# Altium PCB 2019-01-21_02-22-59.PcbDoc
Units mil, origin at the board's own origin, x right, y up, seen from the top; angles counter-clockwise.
Board outline 1500 x 2000 mil, 4 copper layers (Top Layer, MidLayer1, MidLayer2, Bottom Layer); 21 components, 11 nets, 49 pads, 30 vias.
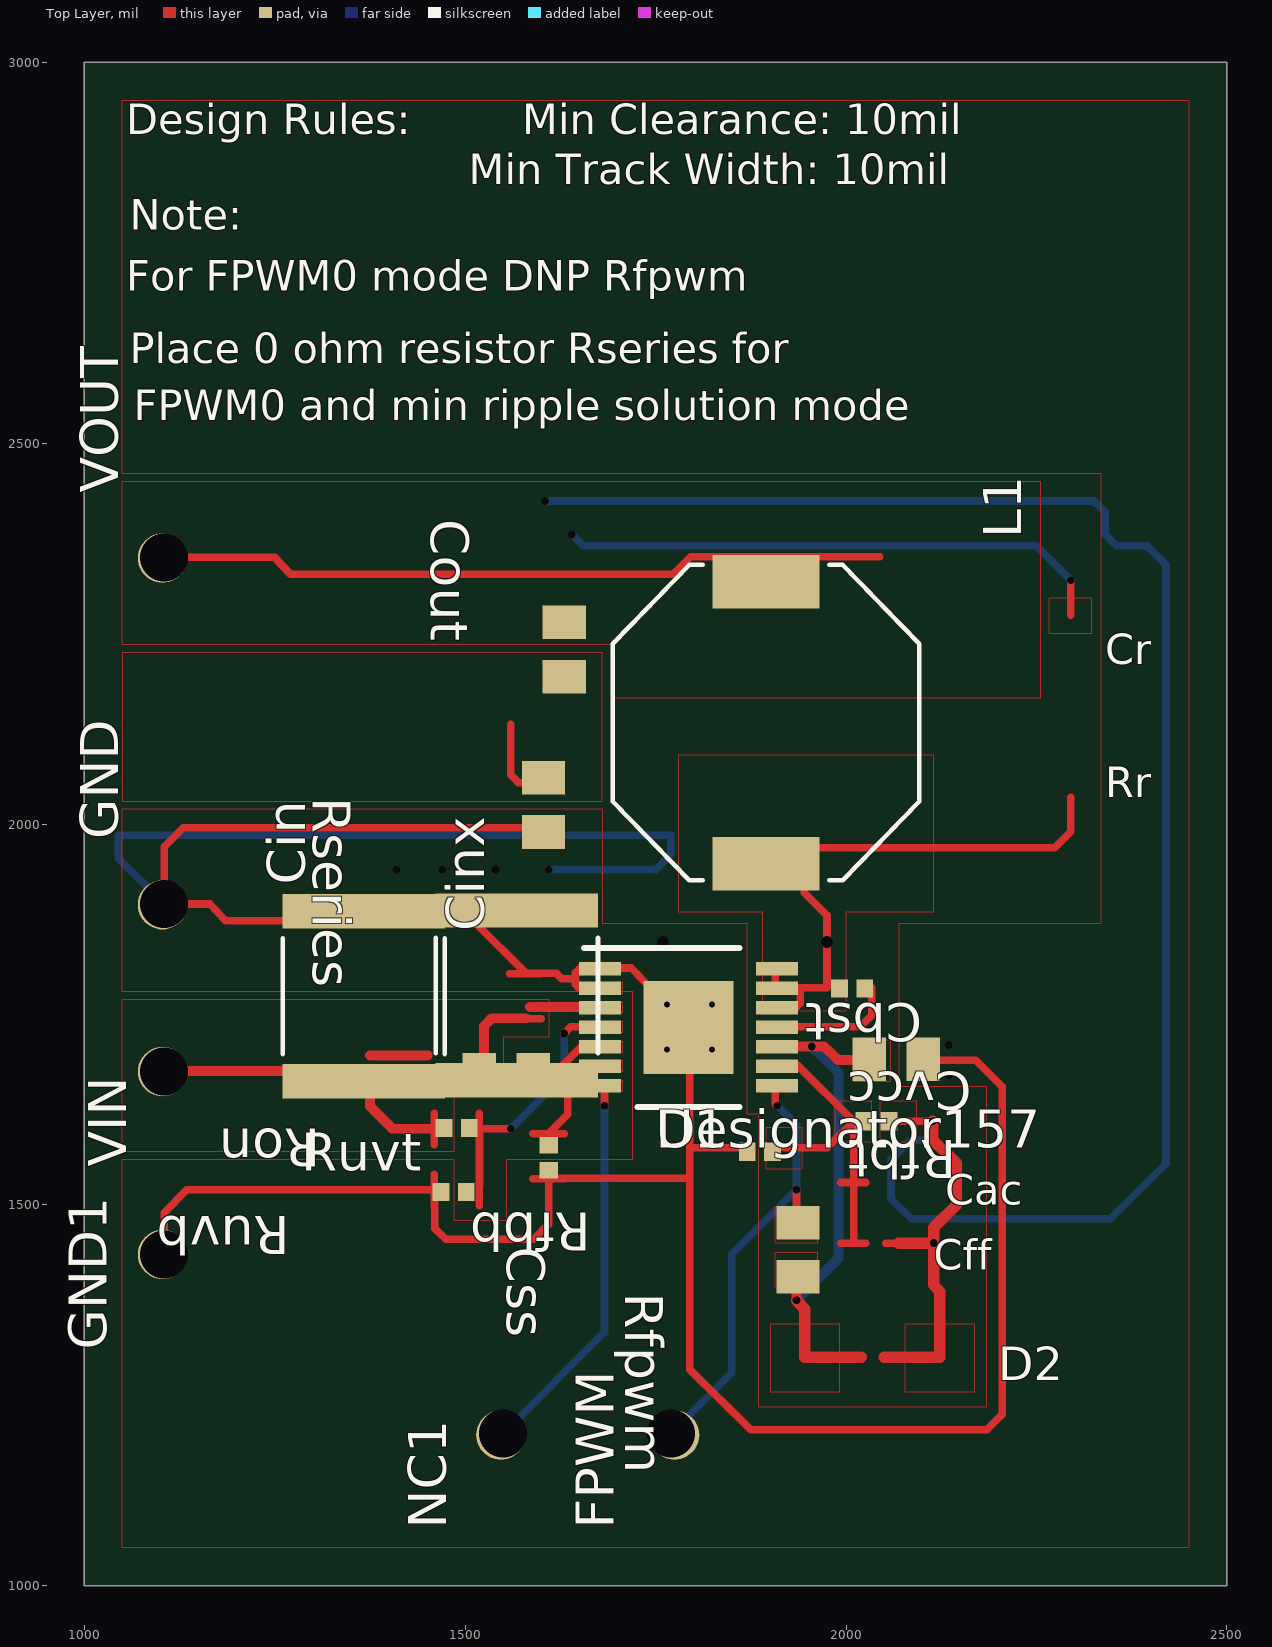
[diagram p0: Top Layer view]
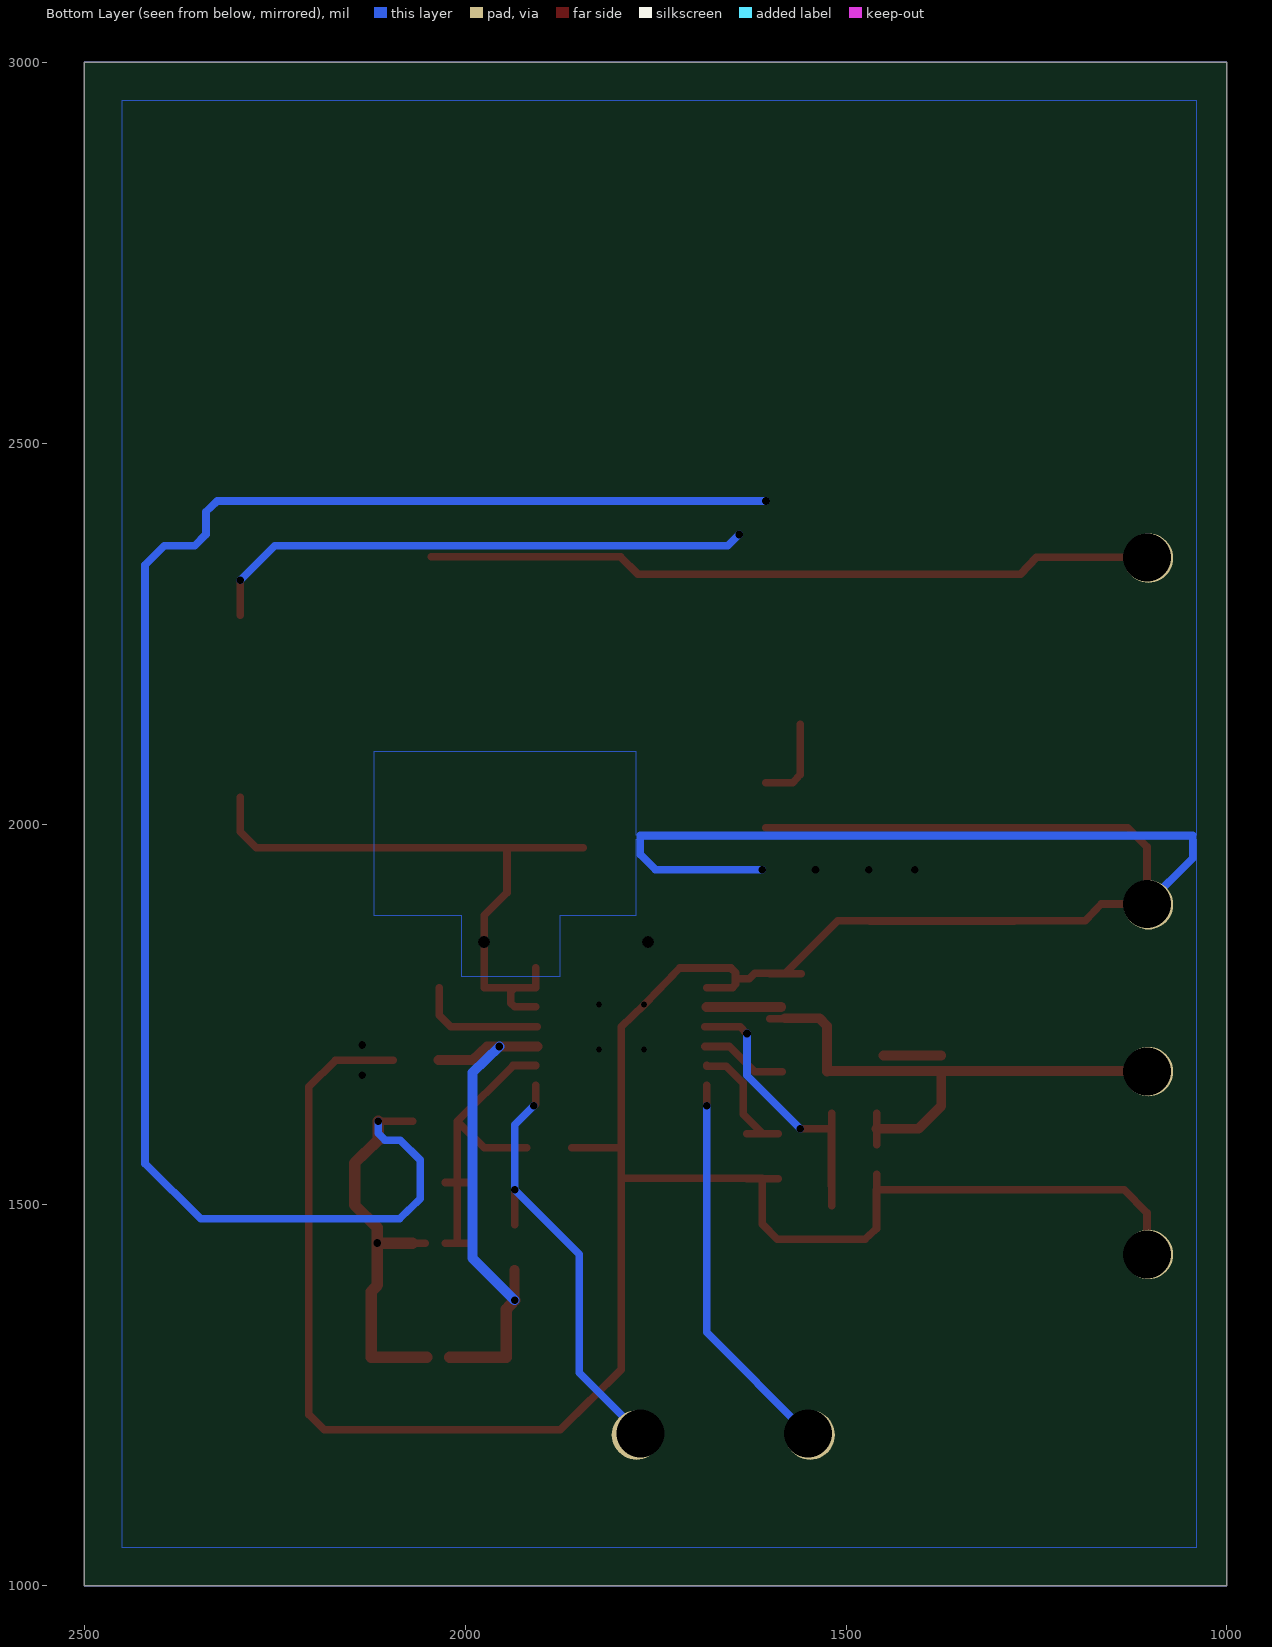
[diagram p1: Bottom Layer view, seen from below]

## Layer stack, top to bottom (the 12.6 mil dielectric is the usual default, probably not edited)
Top Layer: signal copper 1.4
Dielectric: core 12.6, FR-4, Dk 4.8
MidLayer1: signal copper 1.4
Dielectric: prepreg 12.6, FR-4, Dk 4.8
MidLayer2: signal copper 1.4
Dielectric: core 12.6, FR-4, Dk 4.8
Bottom Layer: signal copper 1.4

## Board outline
1000,1000 2500,1000 2500,3000 1000,3000

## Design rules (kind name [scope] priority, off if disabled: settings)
PlaneConnect [All] p0: scope1count=1 scope1_0_kind=Board scope1_0_value=Board scope2count=1 scope2_0_kind=Board scope2_0_value=Board commentlength=0 planeconnectstyle=Direct reliefexpansion=20 reliefentries=4 reliefconductorwidth=10 reliefairgap=10
PlaneConnect [All] p1: planeconnectstyle=Direct reliefexpansion=20 reliefentries=4 reliefconductorwidth=10 reliefairgap=10
PolygonConnect [All] p0: scope1count=1 scope1_0_kind=Board scope1_0_value=Board scope2count=1 scope2_0_kind=Board scope2_0_value=Board commentlength=0 connectstyle=Direct reliefconductorwidth=10 reliefentries=4 polygonreliefangle="90 Angle"
PolygonConnect [All] p1: connectstyle=Direct reliefconductorwidth=10 reliefentries=4 polygonreliefangle="90 Angle"

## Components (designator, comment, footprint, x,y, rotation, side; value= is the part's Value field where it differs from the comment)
Cbst "" 0402 2008,1784 r180 top
Cin "" 2220_200 1367,1774 r90 top
Cinx "" 2220_200 1568,1775 r90 top
Cout "" 0805 1630,2229 r270 top
Css "" 0402 1610,1562 r270 top
Cvcc "" 0805 2066,1691 r180 top
FPWM "" TP-1502 1775,1198 r90 top
GND "" TP-1502 1103,1894 r90 top
GND1 "" TP-1502 1103,1435 r90 top
L1 "" MSS1038 1895,2133 r90 top
NC1 "" TP-1502 1547,1198 r90 top
Rfbb "" 0402 1887,1570 r180 top
Rfbt "" 0402 2040,1610 r180 top
Rfpwm "" 0805 1937,1441 r270 top
Ron "" 0805 1554,1671 r180 top
Rseries "" 0805 1603,2025 r270 top
Ruvb "" 0402 1485,1517 r180 top
Ruvt "" 0402 1489,1601 r0 top
U1 "" PWP0014A_N 1793,1733 r0 top
VIN "" TP-1502 1103,1675 r90 top
VOUT "" TP-1502 1103,2349 r90 top

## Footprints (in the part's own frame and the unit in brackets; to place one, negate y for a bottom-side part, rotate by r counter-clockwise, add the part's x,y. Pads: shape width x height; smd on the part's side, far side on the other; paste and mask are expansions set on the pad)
0402 [mil]
  rect 22x24 smd: 1(-16.5,0) 2(16.5,0)
0805 [mil]
  rect 44x57 smd: 1(-35.5,0) 2(35.5,0)
2220_200 [mil]
  rect 45x213 smd: 1(-111.5,0) 2(111.5,0)
  silkscreen extent -76,-106 76,106
MSS1038 [mil]
  rect 70x140 smd: 1(-185,0) 2(185,0)
  silkscreen extent -207,-201 207,201
PWP0014A_N [mm]
  rect 1.4x0.45 smd: 1(-2.95,1.95) 2(-2.95,1.3) 3(-2.95,0.65) 4(-2.95,0) 5(-2.95,-0.65) 6(-2.95,-1.3) 7(-2.95,-1.95) 8(2.95,-1.95) 9(2.95,-1.3) 10(2.95,-0.65) 11(2.95,0) 12(2.95,0.65) 13(2.95,1.3) 14(2.95,1.95)
  rect 3x3.1 smd: 15(0,0)
  silkscreen extent -3.47,-2.65 1.7,2.65
TP-1502 [mil]
  round 65 / inner round 0 / far side round 65 hole 32: 1(0,0)

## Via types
v1: diameter 0, hole 10, Top Layer to Bottom Layer, 18 vias
v2: diameter 0, hole 63, Top Layer to Bottom Layer, 6 vias
v3: diameter 0, hole 8, Top Layer to Bottom Layer, 4 vias
v4: diameter 0, hole 16, Top Layer to Bottom Layer, 2 vias

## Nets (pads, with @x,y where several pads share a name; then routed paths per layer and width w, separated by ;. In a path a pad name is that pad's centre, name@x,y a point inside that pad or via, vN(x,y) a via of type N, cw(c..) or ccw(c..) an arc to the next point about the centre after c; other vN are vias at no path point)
0: Cin.2 Cinx.2 Cout.2 Css.2 Cvcc.1 FPWM.1 GND1.1 GND.1 Rfbb.2 Rfpwm.1 Rseries.1 Rseries.2 Ruvb.2 U1.1 U1.2 U1.8 U1.15 | length 5854.8
  Top Layer w10: v2(1105,1435) 1105,1490 1135,1520 1460,1520 1460,1469 1475,1455 1590,1455 1610,1475 1610,1535 1794,1535 1795,1535 ; Cin.2@1279,1872.5 Cin.2@1469,1872.5 ; 1459.5,1499 1459.5,1540 ; 1559,1803.5 1600,1803.5 ; 1560,2131 1560,2065 1570,2054 Rseries.1@1605,2054 ; 1589,1534.5 1630,1534.5 ; Rseries.2@1605,1995 1130,1995 1105,1970 v2(1105,1895) 1165,1895 1186,1873 1375,1873 1511,1873 1580,1804 1620,1804 1627,1797 1645,1797 ; U1.2@1683,1785 1649,1785 1645,1790 1645,1797 ; Rfbb.2@1860,1575 1795,1575 ; U1.8@1907,1657 1907,1632 v1(1910,1630) ; Rfpwm.1@1935,1474 v1(1935,1520) ; Cvcc.1@2094,1690 2170,1690 2205,1655 2205,1225 2185,1205 1875,1205 1795,1284 1795,1535 ; 1645,1797 1645,1805 1651,1811 1683,1811 1718,1811 v3(1765,1763) 1795,1734 1795,1575 ; 1795,1535 1795,1575
  Bottom Layer w10: v2(1105,1895) 1045,1955 1045,1985 1770,1985 1770,1960 1750,1940 v1(1610,1940) ; v2(1770,1200) 1850,1280 1850,1435 v1(1935,1520) 1935,1605 v1(1910,1630)
  other v1: 2135,1670 2135,1710 1410,1940 1470,1940 1540,1940
  other v3: 1765,1704 1824,1704 1824,1763
  other v4: 1760,1845
1: Cbst.1 U1.11 | length 171.2
  Top Layer w10: U1.11@1905,1734 1907,1734 2019,1734 2034,1749 Cbst.1@2034,1785
2: Ruvb.1 Ruvt.2 U1.4 | length 410.7
  Top Layer w10: 1518.5,1499 1518.5,1540 ; 1518.5,1579 1518.5,1620 ; 1519,1525 1519,1600 v1(1560,1600) ; v1(1630,1725) 1639,1734 1683,1734 U1.4@1685,1734
  Bottom Layer w10: v1(1560,1600) 1630,1670 v1(1630,1725)
3: Css.1 U1.6 | length 175.5
  Top Layer w10: 1589,1593.5 1630,1593.5 ; 1610,1594 1635,1619 1635,1660 1657,1682 1683,1682 U1.6@1683,1683
4: Ron.1 U1.5 | length 78.7
  Top Layer w10: 1620,1675 1653,1708 1683,1708 U1.5@1685,1708
5: Cin.1 Cinx.1 Ron.2 Ruvt.1 U1.3 VIN.1 | length 1165.2
  Top Layer w10: Cin.1@1279,1675.5 Cin.1@1469,1675.5 ; 1459.5,1579 1459.5,1620 ; 1559,1744.5 1600,1744.5 ; Cinx.1@1584,1675 Cinx.1@1620,1675
  Top Layer w13: v2(1105,1675) 1106,1676 Cin.1@1375,1676 ; 1375,1696 1451,1696 ; 1460,1600 1405,1600 1375,1630 Cin.1@1375,1676 ; 1580,1745 1535,1745 1525,1735 1525,1675 1523,1676 Cin.1@1375,1676 ; 1585,1760 U1.3@1683,1760
6: Cvcc.2 Rfpwm.2 U1.10 | length 701
  Top Layer w13: U1.10@1905,1708 1907,1708 v1(1955,1708) 1971,1708 1990,1690 Cvcc.2@2035,1690 ; v1(1935,1375) Rfpwm.2@1935,1415
  Top Layer w15: v1(1935,1375) 1946,1363 1946,1300 2020,1300
  Bottom Layer w13: v1(1935,1375) 1990,1430 1990,1674 v1(1955,1708)
7: Cbst.2 L1.1 U1.12 U1.13 U1.14 | length 950.3
  Top Layer w10: L1.1@1845,1969 2044,1969 ; U1.12@1907,1760 1935,1760 1940,1765 1940,1780 U1.13@1935,1785 ; U1.14@1907,1811 1907,1785 1934,1785 U1.13@1935,1785 ; 2295,2035 2295,1990 2274,1969 1945,1969 1945,1910 1975,1880 v4(1975,1845) 1975,1785 U1.13@1935,1785
8: Cout.1 L1.2 Rfbt.1 VOUT.1 | length 4510
  Top Layer w10: v2(1105,2350) 1250,2350 1271,2328 1565,2328 1773,2328 1796,2351 L1.2@1945,2351 ; L1.2@1845,2351 2044,2351 ; 2052,1449.5 2085,1449.5 ; 2069,1610 v1(2114,1610) ; 2295,2274 v1(2295,2320)
  Top Layer w15: 2050,1300 2123,1300 2123,1386 2115,1395 v1(2115,1450) ; 2069,1450 v1(2115,1450) ; v1(2114,1610) 2114,1585 2145,1555 2145,1500 2115,1470 v1(2115,1450)
  Bottom Layer w10: v1(1605,2424) 2325,2424 2340,2410 2340,2380 2355,2365 2395,2365 2420,2340 2420,1554 2347,1482 2086,1482 2059,1508 2059,1559 2085,1585 2105,1585 2114,1594 v1(2114,1610) ; v1(1640,2380) 1655,2365 2250,2365 v1(2295,2320)
9: Rfbb.1 Rfbt.2 U1.9 | length 464.7
  Top Layer w10: U1.9@1907,1683 1937,1683 2010,1610 ; 1919,1575 1975,1575 2010,1610 ; 1993,1449.5 2026,1449.5 ; 1993,1529.5 2026,1529.5 ; 2010,1450 2010,1530 2010,1610
11: NC1.1 U1.7 | length 512.1
  Top Layer w10: v1(1683,1630) U1.7@1683,1657
  Bottom Layer w10: v2(1550,1200) 1683,1333 v1(1683,1630)

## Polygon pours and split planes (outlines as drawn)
6 on Top Layer " " (solid, pour order 0): 1907,1391 1907,1438 1962,1438 1962,1391
9 on Top Layer " " (solid, pour order 1): 1986,1582 1986,1637 2033,1637 2033,1582
8 on Top Layer " " (solid, pour order 2): 2045,1582 2045,1637 2092,1637 2092,1582
9 on Top Layer " " (solid, pour order 3): 1895,1547 1895,1602 1942,1602 1942,1547
6 on Top Layer " " (solid, pour order 4): 2011,1662 2011,1717 2058,1717 2058,1662
8 on Top Layer " " (solid, pour order 5): 2267,2250 2267,2297 2322,2297 2322,2250
5 on Top Layer " " (solid, pour order 7): 1659,1752 1659,1767 1706,1767 1706,1752
2 on Top Layer " " (solid, pour order 8): 1659,1726 1659,1741 1706,1741 1706,1726
4 on Top Layer " " (solid, pour order 9): 1659,1700 1659,1715 1706,1715 1706,1700
3 on Top Layer " " (solid, pour order 10): 1659,1675 1659,1690 1706,1690 1706,1675
11 on Top Layer " " (solid, pour order 11): 1659,1649 1659,1664 1706,1664 1706,1649
7 on Top Layer " " (solid, pour order 12): 1883,1803 1883,1818 1930,1818 1930,1803
7 on Top Layer " " (solid, pour order 13): 1883,1777 1883,1792 1930,1792 1930,1777
7 on Top Layer " " (solid, pour order 14): 1883,1752 1883,1767 1930,1767 1930,1752
1 on Top Layer " " (solid, pour order 15): 1883,1726 1883,1741 1930,1741 1930,1726
6 on Top Layer " " (solid, pour order 16): 1883,1700 1883,1715 1930,1715 1930,1700
9 on Top Layer " " (solid, pour order 17): 1883,1675 1883,1690 1930,1690 1930,1675
8 on Top Layer " " (solid, pour order 18): 2078,1254 2078,1344 2168,1344 2168,1254
6 on Top Layer " " (solid, pour order 19): 1901,1254 1901,1344 1991,1344 1991,1254
7 on Top Layer " " (solid, pour order 20): 1780,2090 1780,1885 1890,1885 1890,1755 2000,1755 2000,1885 2115,1885 2115,2090
8 on Top Layer " " (solid, pour order 21): 2255,2165 1695,2165 1695,2235 1050,2235 1050,2450 2255,2450
5 on Top Layer " " (solid, pour order 22): 1610,1770 1610,1720 1550,1720 1550,1645 1485,1645 1485,1570 1050,1570 1050,1770
0 on Top Layer " " (solid, pour order 23): 1907,1450 1907,1497 1962,1497 1962,1450
0 on Top Layer " " (solid, pour order 24): 1659,1777 1659,1792 1706,1792 1706,1777
0 on Top Layer " " (solid, pour order 25): 1883,1649 1883,1664 1930,1664 1930,1649
0 on Top Layer " " (solid, pour order 27): 1680,2030 1680,2225 1050,2225 1050,2030
0 on Top Layer " " (solid, pour order 28): 1050,2020 1680,2020 1680,1870 1870,1870 1870,1620 1885,1620 1885,1235 2185,1235 2185,1655 2070,1655 2070,1870 2335,1870 2335,2460 1050,2460 1050,2950 2450,2950 2450,1050 1050,1050 1050,1560 1485,1560 1485,1480 1555,1480 1555,1560 1720,1560 1720,1780 1625,1780 1050,1780
0 on Bottom Layer " " (solid, pour order 26): 2450,1050 2450,2950 1040,2950 1040,1985 1775,1985 1775,2095 2120,2095 2120,1880 2005,1880 2005,1800 1875,1800 1875,1880 1775,1880 1775,1980 1040,1980 1040,1050

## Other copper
Multi-Layer:
  the board outline again, w1

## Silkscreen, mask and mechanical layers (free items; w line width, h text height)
Top Overlay:
  text "Design Rules:" at 1055,2905 h40
  text "Min Clearance: 10mil" at 1575,2905 h40
  text "Min Track Width: 10mil" at 1505,2840 h40
  text "Note:" at 1060,2780 h40
  text "For FPWM0 mode DNP Rfpwm" at 1055,2700 h40
  text "Place 0 ohm resistor Rseries for" at 1060,2605 h40
  text "FPWM0 and min ripple solution mode" at 1065,2530 h40
  text "Cr" at 2340,2210 h40
  text "Rr" at 2340,2035 h40
  text "Cac" at 2130,1500 h40
  text "Cff" at 2115,1415 h40
  text "D2" at 2200,1270 h44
